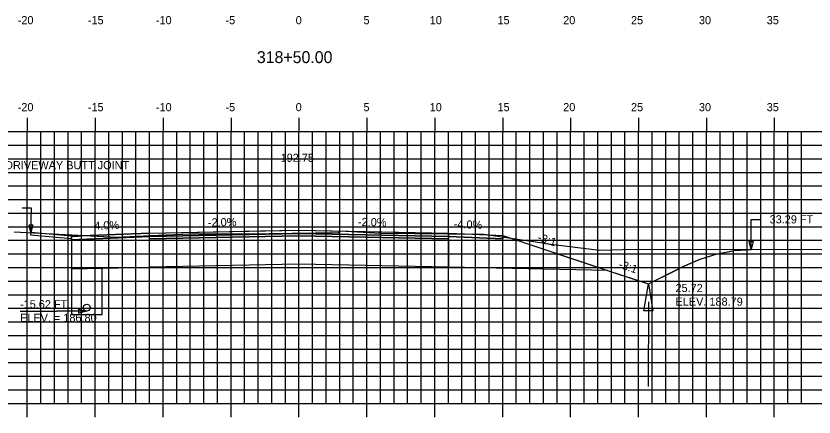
# Model space of a CAD drawing. Extents: x 1139207 to 1139377, y 608981 to 609091.
# Drawn here: x 1139268.9 to 1139327.6, y 609019.3 to 609048.8 of the extents above; entities that cross this region are included whole.
import ezdxf

# ---------------------------------------------------------------- set-up
doc = ezdxf.new("R2010")
doc.units = 0
for name, color, linetype in [('ANNOTATION', 7, 'Continuous'), ('D_Drainage_Ditch_Line', 7, 'Continuous'), ('D_Drainage_Underdrain', 7, 'Continuous'), ('D_Drainage_Underdrain_06in', 7, 'Continuous'), ('D_Roadway_Centerline', 7, 'Continuous'), ('D_Roadway_Centerline_Text', 7, 'Continuous'), ('D_Roadway_Edge_Shoulder', 7, 'Continuous'), ('D_Roadway_Edge_TW', 7, 'Continuous'), ('D_Roadway_Pavement', 7, 'Continuous'), ('D_Roadway_SlopeLines', 7, 'Continuous'), ('D_Roadway_SubGrade', 7, 'Continuous'), ('D_Text_Standard', 7, 'Continuous'), ('H_V ANNOTATION', 7, 'Continuous'), ('MAJOR', 7, 'Continuous'), ('MINOR', 7, 'Continuous'), ('S_Roadway_Centerline', 7, 'Continuous')]:
    doc.layers.add(name, color=color, linetype=linetype)

msp = doc.modelspace()

# ---------------------------------------------------------------- linework, layer by layer
msp.add_lwpolyline([(1139272.955, 609032.631), (1139272.955, 609032.631), (1139272.956, 609032.631), (1139273.008, 609032.634), (1139273.16, 609032.64), (1139273.38, 609032.648), (1139273.455, 609032.651), (1139273.519, 609032.654), (1139273.705, 609032.661), (1139277.425, 609032.81), (1139278.705, 609032.861), (1139286.889, 609033.025), (1139289.705, 609033.081), (1139297.889, 609032.918), (1139300.705, 609032.861), (1139303.681, 609032.742), (1139304.705, 609032.701), (1139310.451, 609030.786), (1139312.429, 609030.127), (1139314.661, 609029.383), (1139315.429, 609029.127), (1139317.33, 609030.078), (1139317.995, 609030.41), (1139318.925, 609030.817), (1139319.245, 609030.957), (1139320.175, 609031.248), (1139320.495, 609031.348), (1139321.425, 609031.523), (1139321.745, 609031.584), (1139322.675, 609031.643), (1139322.995, 609031.663)])
at = {"layer": 'D_Drainage_Ditch_Line'}
msp.add_line((1139315.429, 609027.815), (1139315.428, 609021.571), dxfattribs=at)
msp.add_lwpolyline([(1139315.757, 609027.159), (1139315.101, 609027.159), (1139315.429, 609029.127)], close=True, dxfattribs=at)
at = {"layer": 'D_Drainage_Underdrain'}
msp.add_lwpolyline([(1139272.956, 609030.246), (1139272.956, 609026.881), (1139275.206, 609026.881), (1139275.206, 609030.291)], close=True, dxfattribs=at)
at = {"layer": 'D_Drainage_Underdrain_06in'}
msp.add_lwpolyline([(1139274.081, 609027.631), (1139274.158, 609027.619), (1139274.228, 609027.584), (1139274.283, 609027.528), (1139274.319, 609027.459), (1139274.331, 609027.381), (1139274.319, 609027.304), (1139274.283, 609027.234), (1139274.228, 609027.179), (1139274.158, 609027.144), (1139274.081, 609027.131), (1139274.004, 609027.144), (1139273.934, 609027.179), (1139273.879, 609027.234), (1139273.843, 609027.304), (1139273.831, 609027.381), (1139273.843, 609027.459), (1139273.879, 609027.528), (1139273.934, 609027.584), (1139274.004, 609027.619)], close=True, dxfattribs=at)
at = {"layer": 'D_Roadway_Edge_Shoulder'}
for points in [[(1139272.956, 609032.631), (1139269.961, 609032.899), (1139269.951, 609032.733), (1139272.956, 609032.464)], [(1139300.705, 609032.861), (1139304.705, 609032.701), (1139304.705, 609032.451), (1139300.705, 609032.611)]]:
    msp.add_lwpolyline(points, close=True, dxfattribs=at)
msp.add_lwpolyline([(1139278.705, 609032.861), (1139273.705, 609032.661), (1139272.956, 609032.631), (1139272.956, 609032.381), (1139278.705, 609032.611), (1139278.705, 609032.861)], dxfattribs=at)
at = {"layer": 'D_Roadway_Edge_TW'}
msp.add_lwpolyline([(1139278.705, 609032.611), (1139278.705, 609032.861), (1139289.705, 609033.081), (1139300.705, 609032.861), (1139300.705, 609032.611), (1139289.705, 609032.831)], close=True, dxfattribs=at)
at = {"layer": 'D_Roadway_Pavement'}
msp.add_lwpolyline([(1139278.705, 609032.445), (1139278.705, 609032.611), (1139289.705, 609032.831), (1139300.705, 609032.611), (1139300.705, 609032.445), (1139289.705, 609032.665)], close=True, dxfattribs=at)
at = {"layer": 'D_Roadway_SlopeLines'}
for points in [[(1139315.429, 609029.127), (1139317.995, 609030.41), (1139319.245, 609030.957), (1139320.495, 609031.348), (1139321.745, 609031.584), (1139322.995, 609031.663)], [(1139312.429, 609030.127), (1139315.429, 609029.127)]]:
    msp.add_lwpolyline(points, dxfattribs=at)
at = {"layer": 'D_Roadway_SubGrade'}
for points in [[(1139272.955, 609031.631), (1139272.956, 609030.246), (1139278.705, 609030.361), (1139278.705, 609032.445), (1139278.705, 609032.611), (1139272.956, 609032.381), (1139272.956, 609032.631), (1139272.955, 609032.631)], [(1139278.705, 609032.445), (1139278.705, 609032.611), (1139272.956, 609032.381), (1139272.956, 609032.631), (1139272.955, 609032.631), (1139272.956, 609030.246), (1139278.705, 609030.361)], [(1139278.705, 609030.361), (1139278.705, 609032.445), (1139289.705, 609032.665), (1139300.705, 609032.445), (1139300.705, 609030.361), (1139289.705, 609030.581)], [(1139300.705, 609032.445), (1139300.705, 609032.611), (1139304.705, 609032.451), (1139304.705, 609032.701), (1139304.705, 609032.701), (1139312.429, 609030.127), (1139300.705, 609030.361)]]:
    msp.add_lwpolyline(points, close=True, dxfattribs=at)
at = {"layer": 'D_Text_Standard'}
msp.add_line((1139269.169, 609027.131), (1139271.845, 609027.131), dxfattribs=at)
for points in [[(1139269.961, 609032.899), (1139270.004, 609034.692), (1139269.324, 609034.692)], [(1139322.996, 609031.661), (1139323, 609033.88), (1139323.68, 609033.88)], [(1139274.081, 609027.131), (1139272.525, 609027.131), (1139271.845, 609027.131)]]:
    msp.add_lwpolyline(points, dxfattribs=at)
for points in [[(1139269.961, 609032.899), (1139269.83, 609033.484), (1139270.121, 609033.477)], [(1139322.996, 609031.661), (1139322.852, 609032.243), (1139323.143, 609032.243)], [(1139274.081, 609027.131), (1139273.499, 609026.986), (1139273.499, 609027.277)]]:
    msp.add_lwpolyline(points, close=True, dxfattribs=at)
at = {"layer": 'MAJOR'}
for p, q in [((1139269.705, 609041.337), (1139269.705, 609040.335)), ((1139274.705, 609041.337), (1139274.705, 609040.335)), ((1139279.705, 609041.337), (1139279.705, 609040.335)), ((1139284.705, 609041.337), (1139284.705, 609040.335)), ((1139289.705, 609041.337), (1139289.705, 609040.335)), ((1139294.705, 609041.337), (1139294.705, 609040.335)), ((1139299.705, 609041.337), (1139299.705, 609040.335)), ((1139304.705, 609041.337), (1139304.705, 609040.335)), ((1139309.705, 609041.337), (1139309.705, 609040.335)), ((1139314.705, 609041.337), (1139314.705, 609040.335)), ((1139319.705, 609041.337), (1139319.705, 609040.335)), ((1139324.705, 609041.337), (1139324.705, 609040.335)), ((1139219.705, 609040.335), (1139359.705, 609040.335)), ((1139219.705, 609040.335), (1139359.705, 609040.335)), ((1139269.705, 609020.335), (1139269.705, 609040.335)), ((1139274.705, 609020.335), (1139274.705, 609040.335)), ((1139279.705, 609020.335), (1139279.705, 609040.335)), ((1139284.705, 609020.335), (1139284.705, 609040.335)), ((1139289.705, 609020.335), (1139289.705, 609040.335)), ((1139294.705, 609020.335), (1139294.705, 609040.335)), ((1139299.705, 609020.335), (1139299.705, 609040.335)), ((1139304.705, 609020.335), (1139304.705, 609040.335)), ((1139309.705, 609020.335), (1139309.705, 609040.335)), ((1139314.705, 609020.335), (1139314.705, 609040.335)), ((1139319.705, 609020.335), (1139319.705, 609040.335)), ((1139324.705, 609020.335), (1139324.705, 609040.335)), ((1139219.705, 609035.335), (1139359.705, 609035.335)), ((1139219.705, 609030.335), (1139359.705, 609030.335)), ((1139219.705, 609025.335), (1139359.705, 609025.335)), ((1139219.705, 609020.335), (1139359.705, 609020.335)), ((1139219.705, 609020.335), (1139359.705, 609020.335)), ((1139269.705, 609019.333), (1139269.705, 609020.335)), ((1139274.705, 609019.333), (1139274.705, 609020.335)), ((1139279.705, 609019.333), (1139279.705, 609020.335)), ((1139284.705, 609019.333), (1139284.705, 609020.335)), ((1139289.705, 609019.333), (1139289.705, 609020.335)), ((1139294.705, 609019.333), (1139294.705, 609020.335)), ((1139299.705, 609019.333), (1139299.705, 609020.335)), ((1139304.705, 609019.333), (1139304.705, 609020.335)), ((1139309.705, 609019.333), (1139309.705, 609020.335)), ((1139314.705, 609019.333), (1139314.705, 609020.335)), ((1139319.705, 609019.333), (1139319.705, 609020.335)), ((1139324.705, 609019.333), (1139324.705, 609020.335))]:
    msp.add_line(p, q, dxfattribs=at)
at = {"layer": 'MINOR'}
for p, q in [((1139270.705, 609020.335), (1139270.705, 609040.335)), ((1139271.705, 609020.335), (1139271.705, 609040.335)), ((1139272.705, 609020.335), (1139272.705, 609040.335)), ((1139273.705, 609020.335), (1139273.705, 609040.335)), ((1139275.705, 609020.335), (1139275.705, 609040.335)), ((1139276.705, 609020.335), (1139276.705, 609040.335)), ((1139277.705, 609020.335), (1139277.705, 609040.335)), ((1139278.705, 609020.335), (1139278.705, 609040.335)), ((1139280.705, 609020.335), (1139280.705, 609040.335)), ((1139281.705, 609020.335), (1139281.705, 609040.335)), ((1139282.705, 609020.335), (1139282.705, 609040.335)), ((1139283.705, 609020.335), (1139283.705, 609040.335)), ((1139285.705, 609020.335), (1139285.705, 609040.335)), ((1139286.705, 609020.335), (1139286.705, 609040.335)), ((1139287.705, 609020.335), (1139287.705, 609040.335)), ((1139288.705, 609020.335), (1139288.705, 609040.335)), ((1139290.705, 609020.335), (1139290.705, 609040.335)), ((1139291.705, 609020.335), (1139291.705, 609040.335)), ((1139292.705, 609020.335), (1139292.705, 609040.335)), ((1139293.705, 609020.335), (1139293.705, 609040.335)), ((1139295.705, 609020.335), (1139295.705, 609040.335)), ((1139296.705, 609020.335), (1139296.705, 609040.335)), ((1139297.705, 609020.335), (1139297.705, 609040.335)), ((1139298.705, 609020.335), (1139298.705, 609040.335)), ((1139300.705, 609020.335), (1139300.705, 609040.335)), ((1139301.705, 609020.335), (1139301.705, 609040.335)), ((1139302.705, 609020.335), (1139302.705, 609040.335)), ((1139303.705, 609020.335), (1139303.705, 609040.335)), ((1139305.705, 609020.335), (1139305.705, 609040.335)), ((1139306.705, 609020.335), (1139306.705, 609040.335)), ((1139307.705, 609020.335), (1139307.705, 609040.335)), ((1139308.705, 609020.335), (1139308.705, 609040.335)), ((1139310.705, 609020.335), (1139310.705, 609040.335)), ((1139311.705, 609020.335), (1139311.705, 609040.335)), ((1139312.705, 609020.335), (1139312.705, 609040.335)), ((1139313.705, 609020.335), (1139313.705, 609040.335)), ((1139315.705, 609020.335), (1139315.705, 609040.335)), ((1139316.705, 609020.335), (1139316.705, 609040.335)), ((1139317.705, 609020.335), (1139317.705, 609040.335)), ((1139318.705, 609020.335), (1139318.705, 609040.335)), ((1139320.705, 609020.335), (1139320.705, 609040.335)), ((1139321.705, 609020.335), (1139321.705, 609040.335)), ((1139322.705, 609020.335), (1139322.705, 609040.335)), ((1139323.705, 609020.335), (1139323.705, 609040.335)), ((1139325.705, 609020.335), (1139325.705, 609040.335)), ((1139326.705, 609020.335), (1139326.705, 609040.335)), ((1139219.705, 609039.335), (1139359.705, 609039.335)), ((1139219.705, 609038.335), (1139359.705, 609038.335)), ((1139219.705, 609037.335), (1139359.705, 609037.335)), ((1139219.705, 609036.335), (1139359.705, 609036.335)), ((1139219.705, 609034.335), (1139359.705, 609034.335)), ((1139219.705, 609033.335), (1139359.705, 609033.335)), ((1139219.705, 609032.335), (1139359.705, 609032.335)), ((1139219.705, 609031.335), (1139359.705, 609031.335)), ((1139219.705, 609029.335), (1139359.705, 609029.335)), ((1139219.705, 609028.335), (1139359.705, 609028.335)), ((1139219.705, 609027.335), (1139359.705, 609027.335)), ((1139219.705, 609026.335), (1139359.705, 609026.335)), ((1139219.705, 609024.335), (1139359.705, 609024.335)), ((1139219.705, 609023.335), (1139359.705, 609023.335)), ((1139219.705, 609022.335), (1139359.705, 609022.335)), ((1139219.705, 609021.335), (1139359.705, 609021.335))]:
    msp.add_line(p, q, dxfattribs=at)
at = {"layer": 'S_Roadway_Centerline'}
msp.add_lwpolyline([(1139268.743, 609032.962), (1139276.277, 609032.574), (1139276.277, 609032.574), (1139276.277, 609032.574), (1139278.743, 609032.693), (1139281.778, 609032.801), (1139285.759, 609032.805), (1139292.65, 609032.921), (1139292.728, 609033.025), (1139295.683, 609032.864), (1139303.307, 609032.796), (1139307.64, 609032.149), (1139307.746, 609032.136), (1139307.838, 609032.108), (1139308.052, 609032.088), (1139311.845, 609031.608), (1139313.562, 609031.651), (1139348.525, 609031.696), (1139359.705, 609031.676)], dxfattribs=at)

# ---------------------------------------------------------------- texts
at = {"layer": 'ANNOTATION'}
msp.add_text('CONSTRUCT DRIVEWAY BUTT JOINT', height=0.6, dxfattribs=at).set_placement((1139262.808, 609037.566))
for s, rotation, p in [('-2.0%', 1.14576, (1139283.008, 609033.348)), ('-2.0%', 358.85424, (1139294.048, 609033.395)), ('-4.0%', 2.29061, (1139274.381, 609033.089)), ('-4.0%', 357.70939, (1139301.089, 609033.247)), ('-3:1', 341.56528, (1139307.228, 609032.315)), ('-3:1', 341.56505, (1139313.194, 609030.326))]:
    msp.add_text(s, height=0.6, rotation=rotation, dxfattribs=at).set_placement(p)
at = {"layer": 'D_Roadway_Centerline'}
for s, p in [('C', (1139289.7, 609033.082)), ('L', (1139289.705, 609033.074))]:
    msp.add_text(s, height=0.0146, dxfattribs=at).set_placement(p)
at = {"layer": 'D_Roadway_Centerline_Text'}
msp.add_text('192.75', height=0.6, dxfattribs=at).set_placement((1139288.354, 609038.113))
at = {"layer": 'D_Text_Standard'}
for s, p in [('33.29 FT', (1139324.359, 609033.58)), ('25.72', (1139317.429, 609028.527)), ('ELEV. 188.79', (1139317.429, 609027.525)), ('-15.62 FT.', (1139269.169, 609027.331)), ('ELEV. = 186.80', (1139269.169, 609026.331))]:
    msp.add_text(s, height=0.6, dxfattribs=at).set_placement(p)
at = {"layer": 'H_V ANNOTATION'}
for s, height, p in [('-20', 0.6, (1139268.999, 609048.235)), ('-15', 0.6, (1139274.162, 609048.235)), ('-10', 0.6, (1139279.17, 609048.235)), ('-5', 0.6, (1139284.296, 609048.235)), ('0', 0.6, (1139289.464, 609048.235)), ('5', 0.6, (1139294.456, 609048.235)), ('10', 0.6, (1139299.331, 609048.235)), ('15', 0.6, (1139304.323, 609048.235)), ('20', 0.6, (1139309.159, 609048.235)), ('25', 0.6, (1139314.151, 609048.235)), ('30', 0.6, (1139319.154, 609048.235)), ('35', 0.6, (1139324.146, 609048.235)), ('318+50.00', 0.875, (1139286.607, 609045.378)), ('-20', 0.6, (1139268.999, 609041.835)), ('-15', 0.6, (1139274.162, 609041.835)), ('-10', 0.6, (1139279.17, 609041.835)), ('-5', 0.6, (1139284.296, 609041.835)), ('0', 0.6, (1139289.464, 609041.835)), ('5', 0.6, (1139294.456, 609041.835)), ('10', 0.6, (1139299.331, 609041.835)), ('15', 0.6, (1139304.323, 609041.835)), ('20', 0.6, (1139309.159, 609041.835)), ('25', 0.6, (1139314.151, 609041.835)), ('30', 0.6, (1139319.154, 609041.835)), ('35', 0.6, (1139324.146, 609041.835))]:
    msp.add_text(s, height=height, dxfattribs=at).set_placement(p)
at = {"layer": 'S_Roadway_Centerline'}
for s, p in [('C', (1139292.722, 609033.025)), ('L', (1139292.728, 609033.017))]:
    msp.add_text(s, height=0.0146, dxfattribs=at).set_placement(p)

doc.saveas('drawing.dxf')
